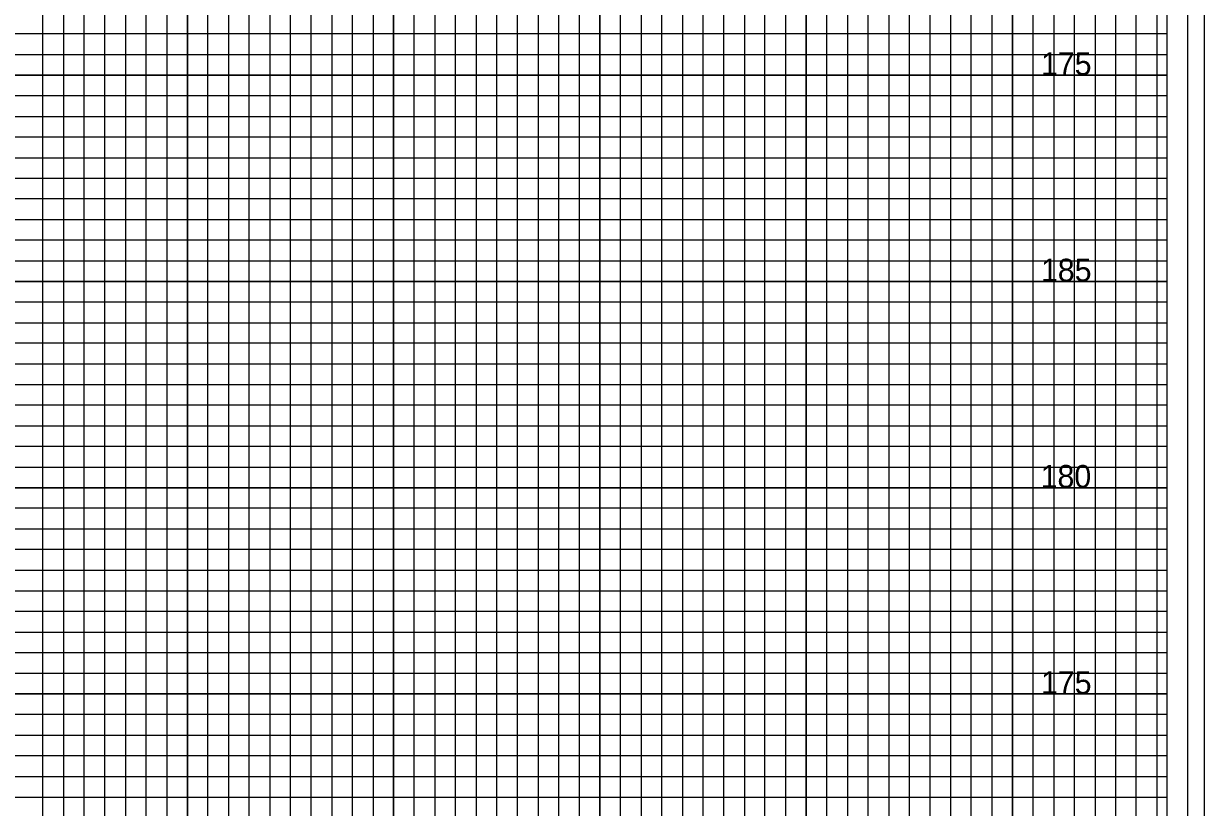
# Model space of a CAD drawing. Extents: x -4 to 103, y -2 to 280.
# Drawn here: x 74.78 to 103.4, y 32.25 to 51.25 of the extents above; entities that cross this region are included whole.
import ezdxf

# ---------------------------------------------------------------- set-up
doc = ezdxf.new("R2010")
doc.units = 0
for name, color, linetype in [('Exist XS Center Line Elevation Label', 7, 'Continuous'), ('Old_Level_63', 7, 'Continuous'), ('Prop XS Dump Level', 7, 'Continuous'), ('Prop XS SE Text', 7, 'Continuous'), ('Prop XS Subgrade Earthwork', 7, 'Continuous'), ('Sheet Plot Border Inside CELL', 7, 'Continuous'), ('Sheet Plot Border Outside CELL', 7, 'Continuous')]:
    doc.layers.add(name, color=color, linetype=linetype)

msp = doc.modelspace()

# ---------------------------------------------------------------- linework, layer by layer
at = {"layer": 'Exist XS Center Line Elevation Label'}
for points in [[(91.25, 0), (91.25, 63.425), (93.75, 63.425), (93.75, 0)], [(96.25, 0), (96.25, 63.425), (98.75, 63.425), (98.75, 0)], [(101.25, 0), (101.25, 63.425)], [(76.25, 0), (76.25, 62), (78.75, 62), (78.75, 0)], [(81.25, 0), (81.25, 62), (83.75, 62), (83.75, 0)], [(86.25, 0), (86.25, 62), (88.75, 62), (88.75, 0)], [(0, 47.5), (102.5, 47.5), (102.5, 50), (0, 50)], [(0, 42.5), (102.5, 42.5), (102.5, 45), (0, 45)], [(0, 37.5), (102.5, 37.5), (102.5, 40), (0, 40)], [(0, 32.5), (102.5, 32.5), (102.5, 35), (0, 35)]]:
    msp.add_lwpolyline(points, dxfattribs=at)
at = {"layer": 'Old_Level_63'}
msp.add_lwpolyline([(102.5, 65), (0, 65), (0, 0), (102.5, 0)], close=True, dxfattribs=at)
at = {"layer": 'Prop XS Dump Level'}
for p, q in [((91.25, 0), (91.25, 63.425)), ((93.75, 0), (93.75, 63.425)), ((96.25, 0), (96.25, 63.425)), ((98.75, 0), (98.75, 63.425)), ((101.25, 0), (101.25, 63.425)), ((76.25, 0), (76.25, 62)), ((78.75, 0), (78.75, 62)), ((81.25, 0), (81.25, 62)), ((83.75, 0), (83.75, 62)), ((86.25, 0), (86.25, 62)), ((88.75, 0), (88.75, 62)), ((0, 50), (102.5, 50)), ((0, 47.5), (102.5, 47.5)), ((0, 45), (102.5, 45)), ((0, 42.5), (102.5, 42.5)), ((0, 40), (102.5, 40)), ((0, 37.5), (102.5, 37.5)), ((0, 35), (102.5, 35)), ((0, 32.5), (102.5, 32.5))]:
    msp.add_line(p, q, dxfattribs=at)
at = {"layer": 'Prop XS SE Text'}
for points in [[(90.25, 0), (90.25, 63.425), (90.75, 63.425), (90.75, 0)], [(91.75, 0), (91.75, 63.425), (92.25, 63.425), (92.25, 0)], [(92.75, 0), (92.75, 63.425), (93.25, 63.425), (93.25, 0)], [(94.25, 0), (94.25, 63.425), (94.75, 63.425), (94.75, 0)], [(95.25, 0), (95.25, 63.425), (95.75, 63.425), (95.75, 0)], [(96.75, 0), (96.75, 63.425), (97.25, 63.425), (97.25, 0)], [(97.75, 0), (97.75, 63.425), (98.25, 63.425), (98.25, 0)], [(99.25, 0), (99.25, 63.425), (99.75, 63.425), (99.75, 0)], [(100.25, 0), (100.25, 63.425)], [(100.25, 63.425), (100.75, 63.425), (100.75, 0), (101.75, 0), (101.75, 63.425), (102.25, 63.425), (102.25, 0)], [(75.25, 0), (75.25, 62), (75.75, 62), (75.75, 0)], [(76.75, 0), (76.75, 62), (77.25, 62), (77.25, 0)], [(77.75, 0), (77.75, 62), (78.25, 62), (78.25, 0)], [(79.25, 0), (79.25, 62), (79.75, 62), (79.75, 0)], [(80.25, 0), (80.25, 62), (80.75, 62), (80.75, 0)], [(81.75, 0), (81.75, 62), (82.25, 62), (82.25, 0)], [(82.75, 0), (82.75, 62), (83.25, 62), (83.25, 0)], [(84.25, 0), (84.25, 62), (84.75, 62), (84.75, 0)], [(85.25, 0), (85.25, 62), (85.75, 62), (85.75, 0)], [(86.75, 0), (86.75, 62), (87.25, 62), (87.25, 0)], [(87.75, 0), (87.75, 62), (88.25, 62), (88.25, 0)], [(89.25, 0), (89.25, 62), (89.75, 62), (89.75, 0)], [(0, 50.5), (102.5, 50.5), (102.5, 51), (0, 51)], [(0, 49), (102.5, 49), (102.5, 49.5), (0, 49.5)], [(0, 48), (102.5, 48), (102.5, 48.5), (0, 48.5)], [(0, 46.5), (102.5, 46.5), (102.5, 47), (0, 47)], [(0, 45.5), (102.5, 45.5), (102.5, 46), (0, 46)], [(0, 44), (102.5, 44), (102.5, 44.5), (0, 44.5)], [(0, 43), (102.5, 43), (102.5, 43.5), (0, 43.5)], [(0, 41.5), (102.5, 41.5), (102.5, 42), (0, 42)], [(0, 40.5), (102.5, 40.5), (102.5, 41), (0, 41)], [(0, 39), (102.5, 39), (102.5, 39.5), (0, 39.5)], [(0, 38), (102.5, 38), (102.5, 38.5), (0, 38.5)], [(0, 36.5), (102.5, 36.5), (102.5, 37), (0, 37)], [(0, 35.5), (102.5, 35.5), (102.5, 36), (0, 36)], [(0, 34), (102.5, 34), (102.5, 34.5), (0, 34.5)], [(0, 33), (102.5, 33), (102.5, 33.5), (0, 33.5)]]:
    msp.add_lwpolyline(points, dxfattribs=at)
at = {"layer": 'Sheet Plot Border Inside CELL'}
msp.add_lwpolyline([(103, 66), (-2.8, 66), (-2.8, -1), (103, -1)], close=True, dxfattribs=at)
at = {"layer": 'Sheet Plot Border Outside CELL'}
msp.add_lwpolyline([(103.4, 67.4), (-3.5, 67.4), (-3.5, -2.425), (103.4, -2.425)], close=True, dxfattribs=at)

# ---------------------------------------------------------------- texts
at = {"layer": 'Prop XS Subgrade Earthwork'}
for s, p in [('175', (99.438, 50)), ('185', (99.438, 45)), ('180', (99.43, 40)), ('175', (99.438, 35))]:
    msp.add_text(s, height=0.55, dxfattribs=at).set_placement(p)

doc.saveas('drawing.dxf')
